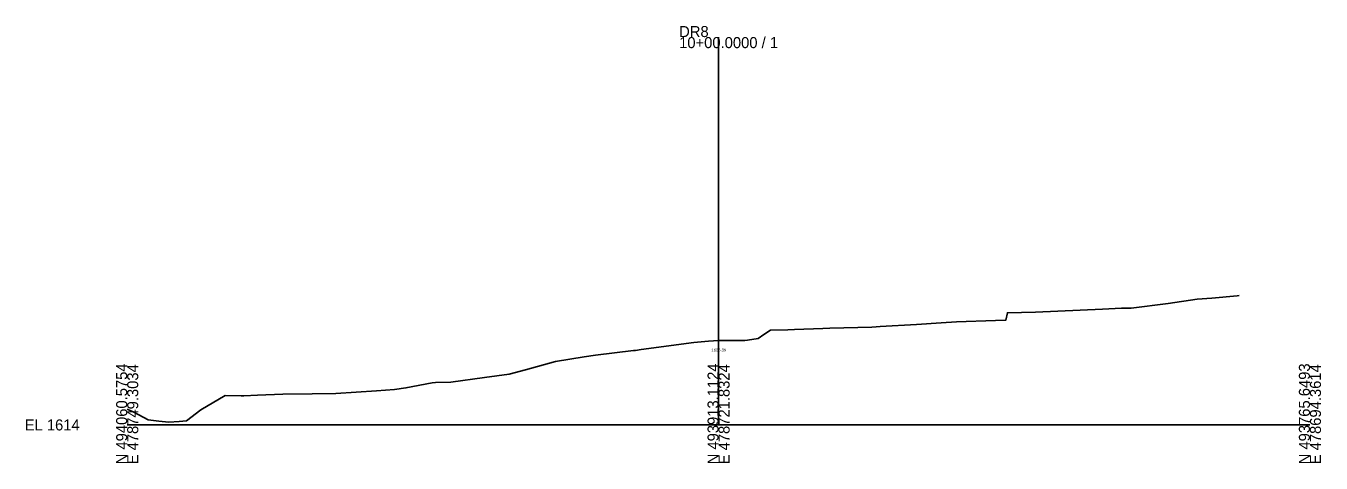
# Model space of a CAD drawing. Extents: x 24 to 353, y -10 to 3552.
# Drawn here: x 24.3 to 352.8, y -9.7 to 101.3 of the extents above; entities that cross this region are included whole.
import ezdxf

# ---------------------------------------------------------------- set-up
doc = ezdxf.new("R2010")
doc.units = 0
for name, color, linetype in [('Exist Cross Section Cell', 7, 'Continuous'), ('Exist XS Center Line Elevation Label', 7, 'Continuous'), ('Exist XS Ground Line', 7, 'Continuous'), ('Scratch_Level_5', 7, 'Continuous')]:
    doc.layers.add(name, color=color, linetype=linetype)

msp = doc.modelspace()

# ---------------------------------------------------------------- linework, layer by layer
at = {"layer": 'Exist Cross Section Cell'}
for p, q in [((200, 0), (200, 98.44)), ((50, 0), (200, 0)), ((200, 0), (350, 0))]:
    msp.add_line(p, q, dxfattribs=at)
at = {"layer": 'Exist XS Ground Line'}
msp.add_lwpolyline([(50, 4), (51.71, 3.21), (55.28, 1.29), (58.01, 0.97), (60.6, 0.69), (63.22, 0.87), (65.02, 1.03), (68.69, 3.81), (74.89, 7.44), (78.88, 7.38), (79.55, 7.38), (83.04, 7.52), (89.48, 7.78), (96.95, 7.89), (102.92, 8), (113.22, 8.68), (117.79, 8.96), (120.68, 9.41), (127.39, 10.65), (128.2, 10.78), (132.07, 10.82), (140.66, 12.01), (146.91, 12.87), (151.06, 13.98), (158.61, 16.09), (165.94, 17.25), (168.78, 17.7), (178.44, 18.86), (178.96, 18.92), (180.36, 19.12), (193.72, 20.94), (197.46, 21.22), (200, 21.39), (200.43, 21.42), (202.53, 21.47), (206.63, 21.42), (207.31, 21.51), (210.01, 21.95), (211.45, 22.92), (213.16, 24.04), (217.59, 24.17), (219.28, 24.21), (226.46, 24.5), (228.24, 24.56), (238.91, 24.83), (240, 24.87), (240.96, 24.94), (250.18, 25.52), (256.5, 25.94), (260.35, 26.17), (270.24, 26.54), (272.91, 26.63), (273.27, 28.46), (280.4, 28.6), (297.42, 29.38), (302.25, 29.65), (304.67, 29.61), (314.09, 30.84), (321.39, 31.88), (325.11, 32.14), (331.57, 32.73), (332.05, 32.81)], dxfattribs=at)
at = {"layer": 'Scratch_Level_5'}
msp.add_lwpolyline([(50, 4), (51.71, 3.21), (55.28, 1.29), (58.01, 0.97), (60.6, 0.69), (63.22, 0.87), (65.02, 1.03), (68.69, 3.81), (74.89, 7.44), (78.88, 7.38), (79.55, 7.38), (83.04, 7.52), (89.48, 7.78), (96.95, 7.89), (102.92, 8), (113.22, 8.68), (117.79, 8.96), (120.68, 9.41), (127.39, 10.65), (128.2, 10.78), (132.07, 10.82), (140.66, 12.01), (146.91, 12.87), (151.06, 13.98), (158.61, 16.09), (165.94, 17.25), (168.78, 17.7), (178.44, 18.86), (178.96, 18.92), (180.36, 19.12), (193.72, 20.94), (197.46, 21.22), (200, 21.39), (200.43, 21.42), (202.53, 21.47), (206.63, 21.42), (207.31, 21.51), (210.01, 21.95), (211.45, 22.92), (213.16, 24.04), (217.59, 24.17), (219.28, 24.21), (226.46, 24.5), (228.24, 24.56), (238.91, 24.83), (240, 24.87), (240.96, 24.94), (250.18, 25.52), (256.5, 25.94), (260.35, 26.17), (270.24, 26.54), (272.91, 26.63), (273.27, 28.46), (280.4, 28.6), (297.42, 29.38), (302.25, 29.65), (304.67, 29.61), (314.09, 30.84), (321.39, 31.88), (325.11, 32.14), (331.57, 32.73), (332.05, 32.81)], dxfattribs=at)

# ---------------------------------------------------------------- texts
at = {"layer": 'Exist Cross Section Cell'}
for s, p in [('10+00.0000 / 1', (190, 95.64)), ('DR8', (190, 98.44)), ('EL 1614', (24, -1.4))]:
    msp.add_text(s, height=2.8, dxfattribs=at).set_placement(p)
for s, p in [('N 494060.5754', (50, -10)), ('E 478749.3034', (52.8, -10)), ('N 493913.1124', (200, -10)), ('E 478721.8324', (202.8, -10)), ('N 493765.6493', (350, -10)), ('E 478694.3614', (352.8, -10))]:
    msp.add_text(s, height=2.8, rotation=90, dxfattribs=at).set_placement(p)
at = {"layer": 'Exist XS Center Line Elevation Label'}
msp.add_text('1635.39', height=0.75, dxfattribs=at).set_placement((198.19, 18.64))

doc.saveas('drawing.dxf')
